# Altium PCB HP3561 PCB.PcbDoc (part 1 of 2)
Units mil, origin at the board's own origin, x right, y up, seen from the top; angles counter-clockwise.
Board outline 2229 x 3254 mil, 4 copper layers (Component Side, Signal Layer 2, Signal Layer 1, Solder Side), stack 33.234 mil thick; 84 components, 95 nets, 407 pads, 246 vias.
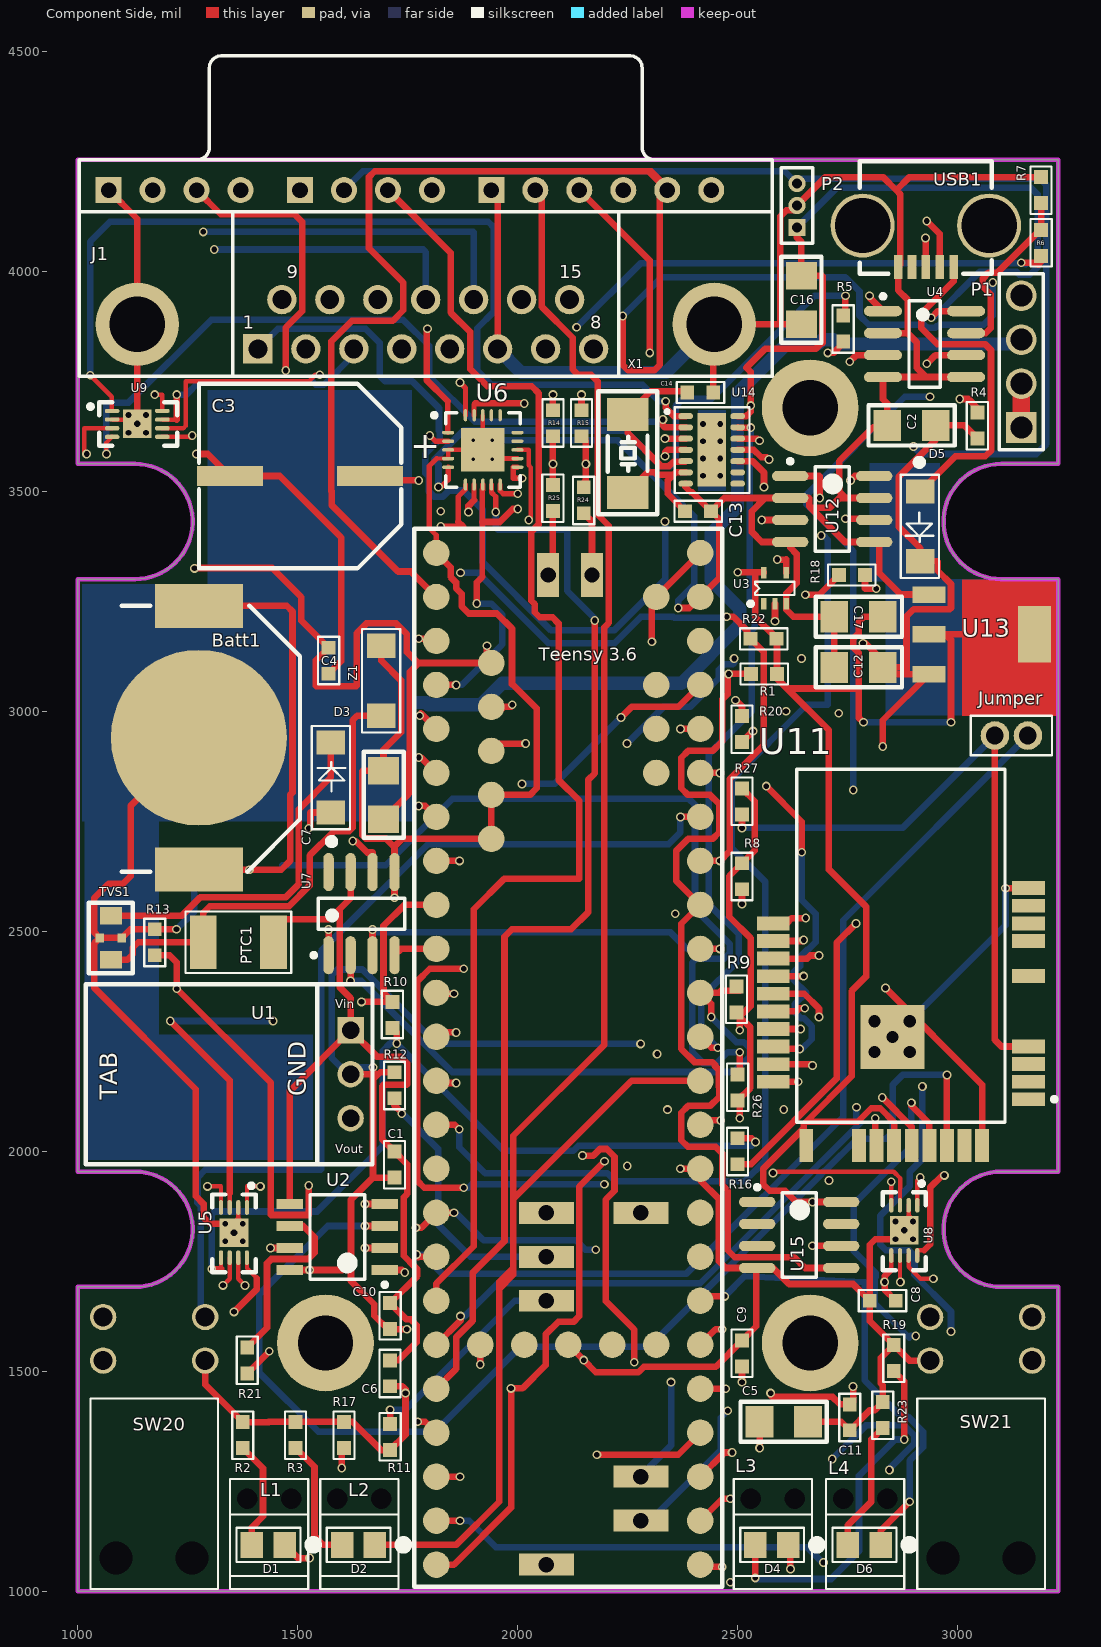
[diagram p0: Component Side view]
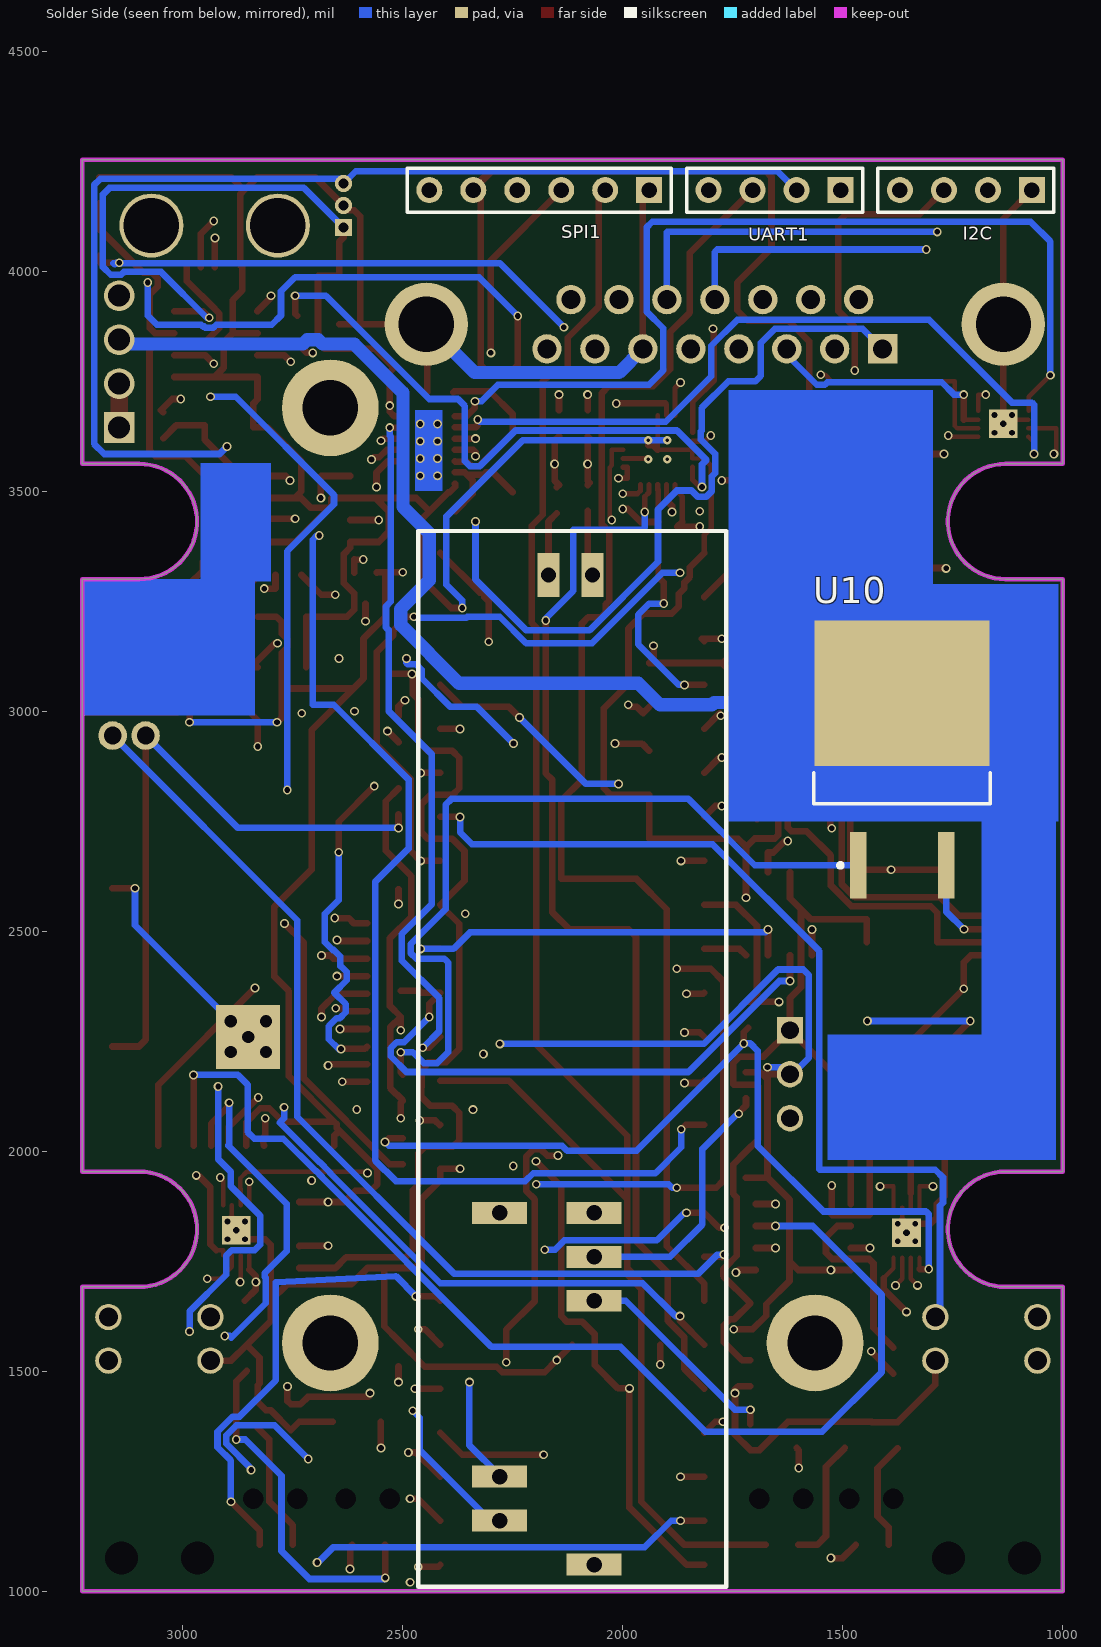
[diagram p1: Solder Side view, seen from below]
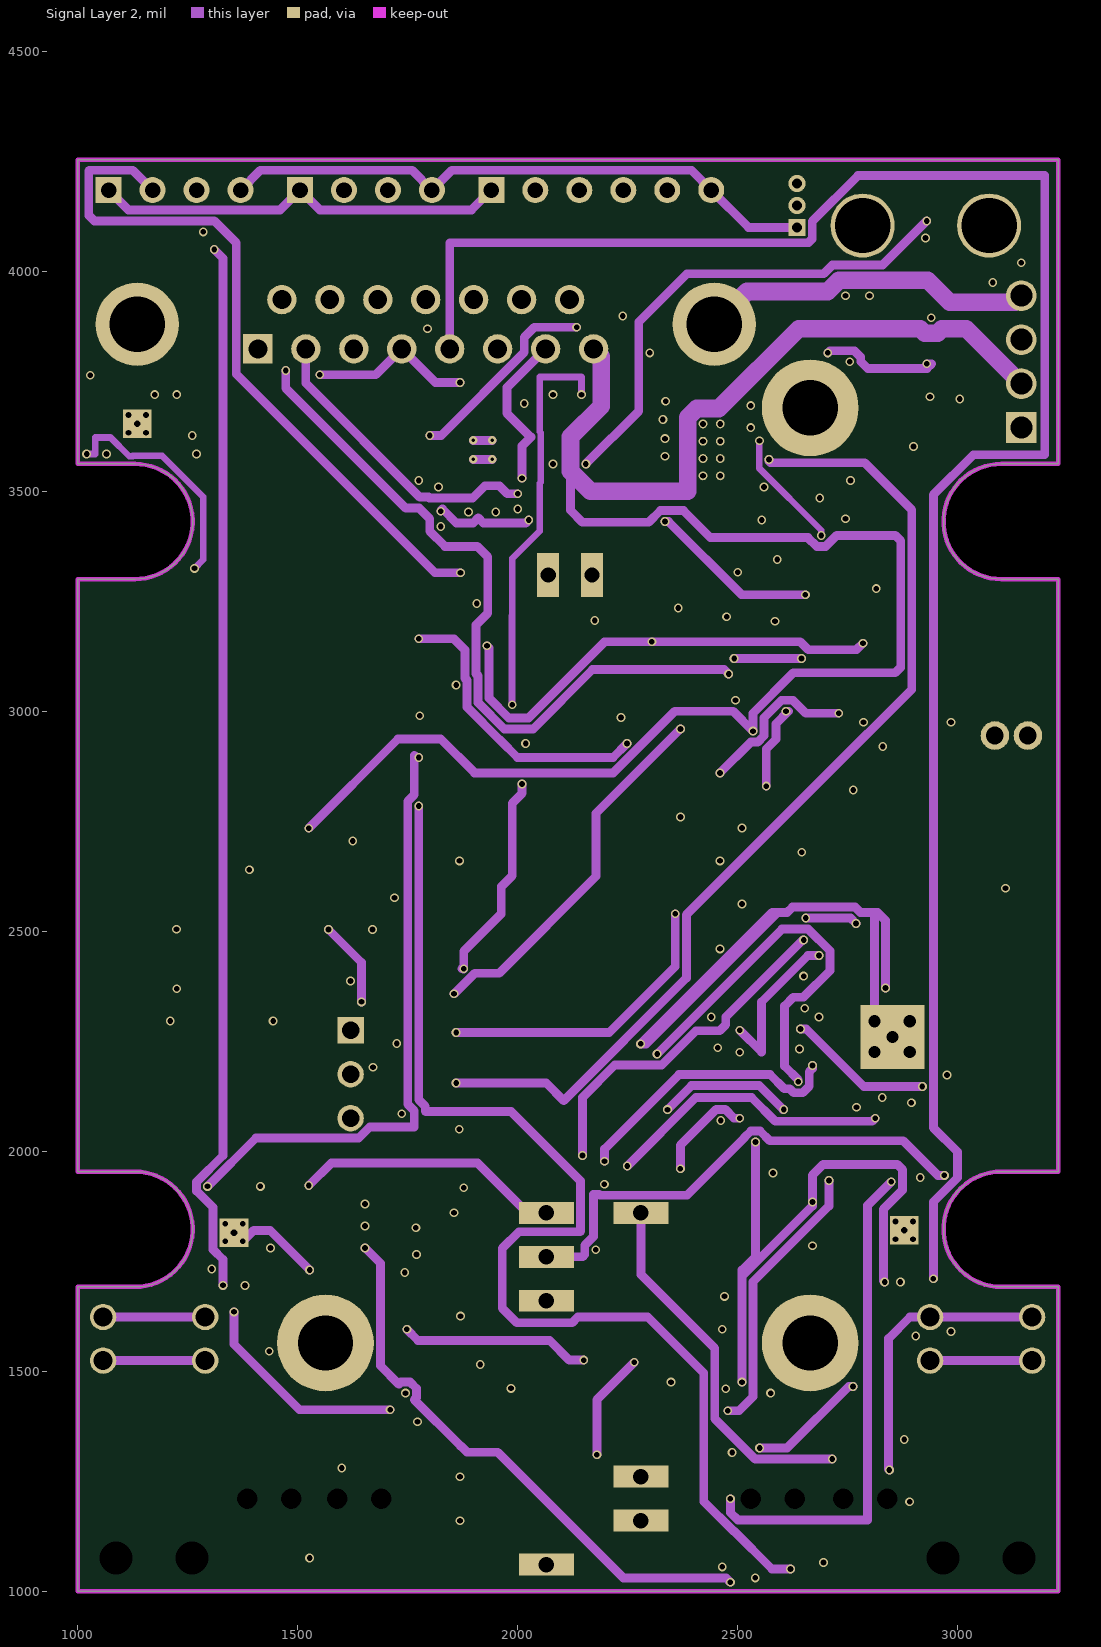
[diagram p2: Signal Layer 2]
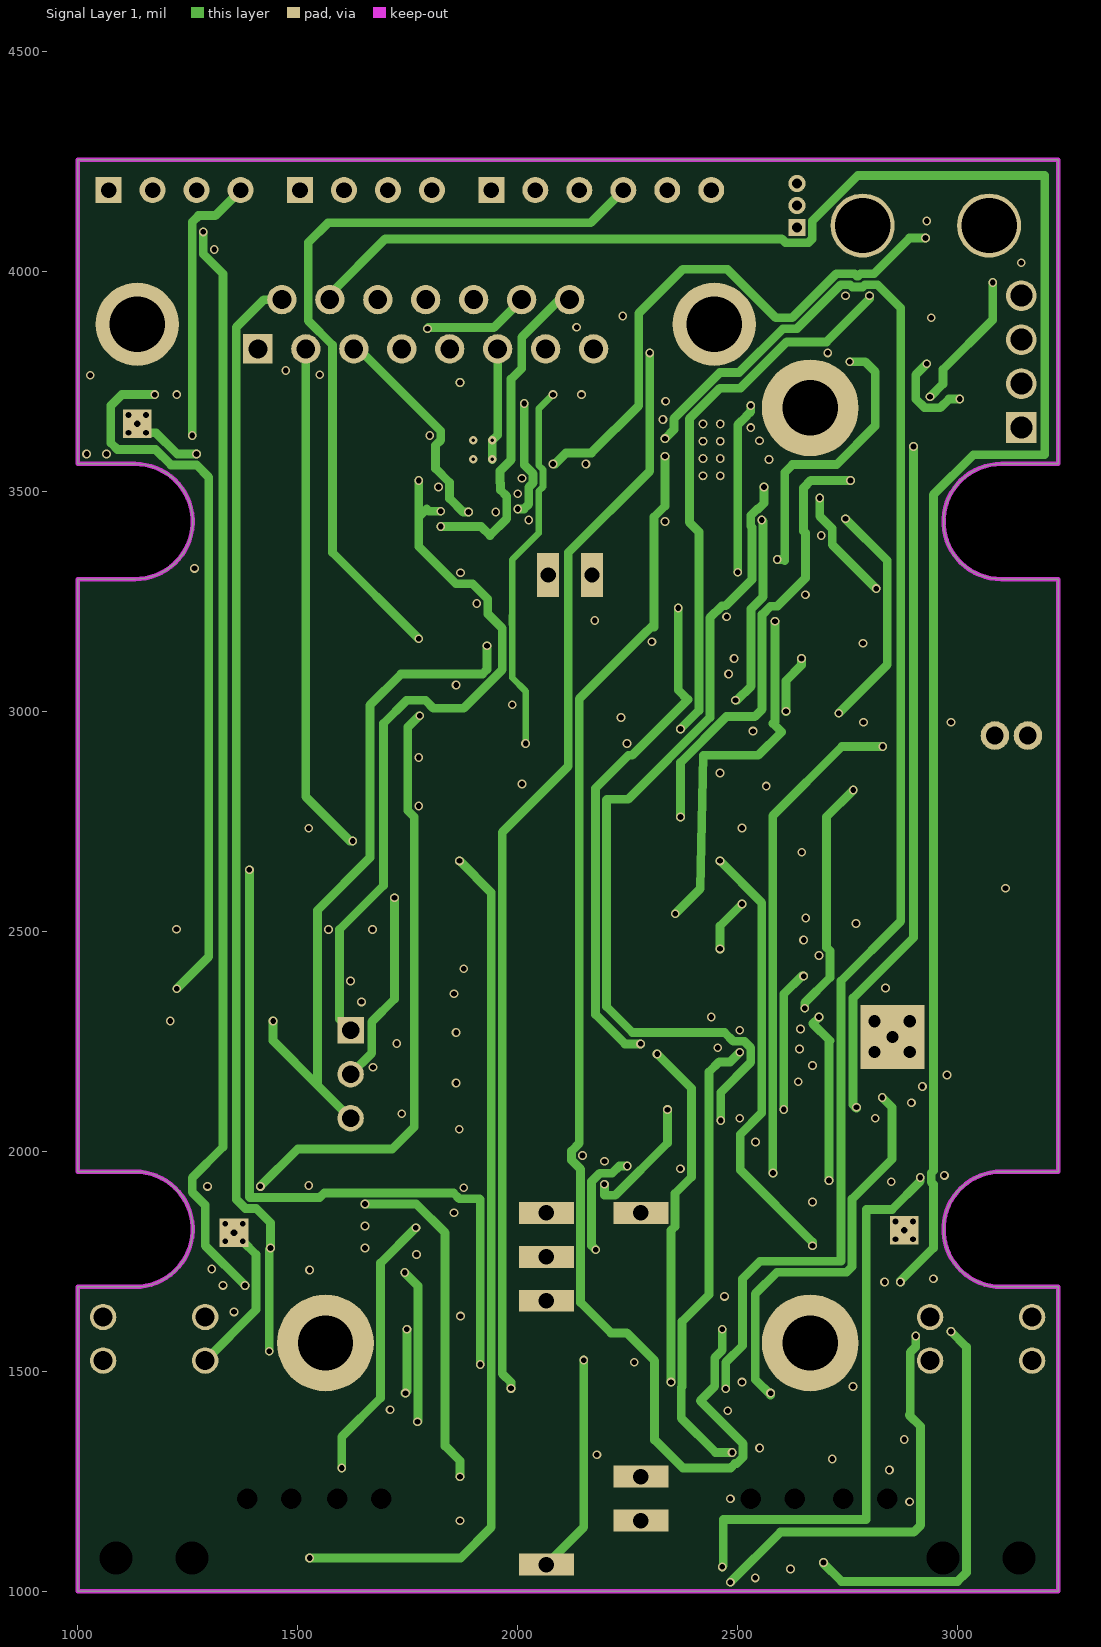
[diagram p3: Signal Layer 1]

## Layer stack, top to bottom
Top Solder: solder mask 0.4, Solder Resist, Dk 3.5
Component Side: signal copper 1.4
Dielectric 1: core 12.6, FR-4, Dk 4.8
Signal Layer 2: signal copper 1.417
Dielectric 5: prepreg 5, Dk 4.2
Signal Layer 1: signal copper 1.417
Dielectric 4: core 10, Dk 4.2
Solder Side: signal copper 1.4
Bottom Solder: solder mask 0.4, Solder Resist, Dk 3.5

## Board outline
1000,1000 1000,1691.5 1130,1691.5 ccw(c1130,1822.5) 1130,1953.5 1000,1953.5 1000,3300.5 1130,3300.5 ccw(c1130,3431.5) 1130,3562.5 1000,3562.5 1000,4254 3229,4254 3229,3562.5 3099,3562.5 ccw(c3099,3431.5) 3099,3300.5 3229,3300.5 3229,1953.5 3099,1953.5 ccw(c3099,1822.5) 3099,1691.5 3229,1691.5 3229,1000

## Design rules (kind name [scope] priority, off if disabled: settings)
Clearance [All] p1: gap=5 ignorepadtopadclearanceinfootprint=FALSE
DiffPairsRouting [All] p1: maxlimit=10 minlimit=10 mostfreqgap=10 toplayer_minwidth=15 toplayer_maxwidth=15 toplayer_prefwidth=15 midlayer1_minwidth=15 midlayer1_maxwidth=15 midlayer1_prefwidth=15 midlayer2_minwidth=15 midlayer2_maxwidth=15 midlayer2_prefwidth=15 bottomlayer_minwidth=15 bottomlayer_maxwidth=15 bottomlayer_prefwidth=15 maxuncoupledlength=500
HoleSize [All] p1: absolutevalues=TRUE maxlimit=250 minlimit=13 maxpercent=80.000 minpercent=20.000
MinimumSolderMaskSliver [All] p1: minsoldermaskwidth=1
PolygonConnect [All] p1: connectstyle=Relief reliefconductorwidth=10 reliefentries=4 polygonreliefangle="90 Angle" airgapwidth=10
RoutingVias [All] p1: holewidth=13 width=20 viastyle="Through Hole" minholewidth=13 minwidth=20 maxholewidth=28 maxwidth=50
SMDNeckDown [All] p1: percent=150.000
SilkToSilkClearance [All] p1: silktosilkclearance=1
SilkToSolderMaskClearance [IsPad] p1: minsilkscreentomaskgap=1 clearancetoexposedcopper=TRUE
SolderMaskExpansion [All] p1: expansion=4
Width [All] p1: maxlimit=100 minlimit=7 preferedwidth=20 toplayer_prefwidth=15 midlayer1_minwidth=10 midlayer2_minwidth=10 bottomlayer_minwidth=10 bottomlayer_prefwidth=15 minimp=50.000000 maximp=50.000000 favimp=50.000000
25 further rules are at their usual default settings.

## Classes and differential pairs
component class "Teensy 3.6 with J1939 - Handheld Rev3": Batt1 C7 C9 C10 C13 C14 D1 D2 D4 D6 I2C L1 L2 L3 L4 P2 R2 R3 R8 R9 R10 R11 R12 R13 R18 R19 R20 R21 R23 SW20 SW21 "Teensy 3.6" U2 U5 U7 U8 U9 U12 U14 UART1 X1
component class "Additional Circuits - Handheld - Rev 3": C1 C2 C3 C4 C5 C6 C8 C11 C12 C16 C17 D3 D5 J1 Jumper P1 PTC1 R1 R4 R5 R6 R7 R14 R15 R16 R17 R22 R24 R25 R26 R27 SPI1 TVS1 U1 U3 U4 U6 U10 U11 U13 U15 USB1 Z1
differential pair "USB D": +"USB D_P" -"USB D_N"
differential pair "Hst USB": +"Hst USB_P" -"Hst USB_N"

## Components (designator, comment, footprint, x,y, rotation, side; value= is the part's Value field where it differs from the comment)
Batt1 "CR1225" "Battery Clip - CR1225" 1275,2940 r270 top locked
C1 "0.1uF" 0603 1720,1969.53 r90 top
C2 "22uF" 1206 2895,3650 r0 top
C3 "100uF" "Elec. Cap - G" 1505,3535 r0 top locked
C4 "10uF" 0603 1570,3115 r270 top
C5 "10uF" 1206 2605,1385 r180 top
C6 "0.1uF" 0603 1710,1495 r90 top
C7 "10uF" 1206 1695,2810 r90 top
C8 "0.1uF" 0603 2830,1660 r0 top
C9 "0.1uF" 0603 2510,1540 r270 top
C10 "1uf" 0603 1710,1625 r270 top
C11 "0.1uF" 0603 2755,1395 r90 top
C12 "22uF" 1206 2775,3100 r0 top
C13 "18pF" 0603 2410,3455 r180 top
C14 "18pF" 0603 2415,3725 r180 top
C16 "22uF" 1206 2645,3935 r90 top
C17 "22uF" 1206 2775,3215 r0 top
D1 "Green" "0805 Polarized" 1435,1105 r180 top
D2 "Red" "0805 Polarized" 1640,1105 r180 top
D3 "ACURA107-HF" "SMA with A and K" 1575,2770 r90 top
D4 "Yellow" "0805 Polarized" 2580,1105 r180 top
D5 "ACURA107-HF" "SMA with A and K" 2915,3500 r270 top
D6 "Blue" "0805 Polarized" 2790,1105 r180 top
I2C "Header 4" HDR1X4#1 1070,4185 r0 bottom
J1 "Vehicle Interface Cable Connector" DSUB1.385-2H15 1790.91,4254.02 r0 top locked
Jumper "WiFi Jumper" "WiFi Jumper" 3160,2945 r180 top
L1 "SLP3" PCBComponent_1 1524,1255 r180 top locked
L2 "SLP3" PCBComponent_1 1729,1255 r180 top locked
L3 "SLP3" PCBComponent_1 2669,1255 r180 top locked
L4 "SLP3" PCBComponent_1 2879,1255 r180 top locked
P1 "Header 4" HDR1X4#2 3145,3645 r90 top
P2 "DNP GP-20U7 JST Header" MHDR1X3 2635,4100 r90 top
PTC1 "PTC RESTTBLE 0.75A" 1812 1365,2475 r0 top
R1 "4.7k" 0603 2560,3085 r180 top
R2 "330" 0603 1375,1354.53 r90 top
R3 "330" 0603 1495,1355 r90 top
R4 "4.7k" 0603 3045,3650 r90 top
R5 "47" 0603 2740,3870 r90 top
R6 "47" 0603 3190,4065 r270 top
R7 "4.7k" 0603 3190,4185 r90 top
R8 "100k" 0603 2510,2625 r90 top
R9 "100k" 0603 2497.5,2345 r270 top
R10 "4.7k" 0603 1715,2310 r270 top
R11 "100k" 0603 1710,1350 r270 top
R12 "100k" 0603 1720,2150 r90 top
R13 "100k" 0603 1175,2475 r90 top
R14 "DNP" 0603 2145,3655 r270 top
R15 "DNP" 0603 2080,3655 r270 top
R16 "100k" 0603 2500,2000 r90 top
R17 "100k" 0603 1605,1355 r90 top
R18 "1k" 0603 2760,3310 r0 top
R19 "330" 0603 2855,1530 r90 top
R20 "1k" 0603 2510,2959.53 r90 top
R21 "4.7k" 0603 1385,1524 r270 top
R22 "4.7k" 0603 2559,3165 r180 top
R23 "330" 0603 2830,1400 r90 top
R24 "47" 0603 2150,3480 r90 top
R25 "47" 0603 2080,3485 r90 top
R26 "100k" 0603 2500,2144.53 r270 top
R27 "100k" 0603 2510,2795 r270 top
SPI1 "Header 6" HDR1X6 1940,4185 r0 bottom
SW20 "PB400" PB400 1057.5,1623 r270 top locked
SW21 "PB400" PB400 2937.5,1623 r270 top locked
"Teensy 3.6" "Teensy 3.6" "Teensy 3.6 Surface Mount" 1815,2060 r0 top locked
TVS1 "Varistor 26V" Transfeed 1075,2535 r270 top
U1 "OKI-78SR" OKI-78SR 1620,2075 r90 top locked
U2 "NCV7356D1R2G" ONSC-SOIC-8-751-07_V 1590,1805 r180 top
U3 "74AHCT1G14" SOT-353 2585,3280 r0 top
U4 "SN75HVD08DR" SOIC-SN8_N 2925,3835 r0 top
U5 "MCP2558" TDFN 1355,1815 r180 top
U6 "ADG1634BCPZ-REEL7" ADI-CP-20-4_N 1920.63,3594.41 r0 top
U7 "MCP2003A-E/SN" SOIC-SN8_N 1645,2540 r90 top
U8 "MCP2558" TDFN 2878.89,1820 r180 top locked
U9 "MCP2558" TDFN 1135,3653.47 r270 top
U10 "BTS141TC" INF-PG-TO263-3-2_N 1365,2890 r90 bottom
U11 "ATML-ATWINC1500-MR210PA-28" ATML-ATWINC1500-MR210PA-28_V 2871,2305.47 r180 top locked
U12 "MOCD207R2M" SOIC-8 2715,3460 r0 top
U13 "NCP1117LPST33" SOT-223 2934.84,3265.55 r270 top
U14 "MCP2517FD" SOP14 2381.89,3671.18 r0 top
U15 "ATECC608A" SOIC-8 2640,1809.53 r0 top
UART1 "Header 4" HDR1X4#1 1505,4185 r0 bottom
USB1 "UX60SC-MB-5S8" "USB Mini UX60S" 2927.99,4250.16 r180 top locked
X1 "16MHz" "XTAL 2 pad" 2250,3497.83 r90 top locked
Z1 "SMA6J" SMA 1690,3149 r270 top

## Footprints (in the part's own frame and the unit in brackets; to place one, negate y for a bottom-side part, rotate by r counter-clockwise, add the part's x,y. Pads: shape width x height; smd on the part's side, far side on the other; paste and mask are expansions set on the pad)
0603 [mm] "0603 SMP Component with outline"
  rect 0.8x0.8 smd: 1(-0.75,0) 2(0.75,0)
  silkscreen extent -1.39,-0.61 1.36,0.61
"0805 Polarized" [mm] "Polarized 0805 with Pin 1 as Anode (+)"
  rect 1.3x1.5 smd: 1(-0.899,0) 2(1.001,0)
  silkscreen extent -2.79,-0.99 1.88,0.99
1206 [mm]
  rect 1.6x1.8 smd: 1(-1.4,0) 2(1.4,0)
  silkscreen extent -2.47,-1.16 2.5,1.15
1812 [mil] "Used for PTC Fuses from belfuse"
  rect 60x122 smd: 1(-80,0)
  rect 62x122 smd: 2(80,0)
  silkscreen extent -120,-70 120,70
ADI-CP-20-4_N [mm] "QFN, 20-Leads, Body 4x4mm, Pitch 0.5mm, Thermal Pad 2.5x2.5mm, IPC Medium Density"
  oval 0.7x0.2 smd: 1(-2,1) 2(-2,0.5) 3(-2,0) 4(-2,-0.5) 5(-2,-1) 11(2,-1) 12(2,-0.5) 13(2,0) 14(2,0.5) 15(2,1)
  oval 0.2x0.7 smd: 6(-1,-2) 7(-0.5,-2) 8(0,-2) 9(0.5,-2) 10(1,-2) 16(1,2) 17(0.5,2) 18(0,2) 19(-0.5,2) 20(-1,2)
  rect 2.5x2.5 smd: 21(0,0)
  silkscreen extent -2.92,-2.15 2.15,2.15, body extent -2,-2 2,2, height 1
ATML-ATWINC1500-MR210PA-28_V [mm] "Module, 28-Leads, Body 21.72x14.73mm, Pitch 1.016mm"
  rect 1.9x0.8 smd: 1(-7.365,4.761) 2(-7.365,3.745) 3(-7.365,2.729) 4(-7.365,1.713) 5(-7.365,-2.351) 6(-7.365,-4.383) 7(-7.365,-5.399) 8(-7.365,-6.415) 9(-7.365,-7.431) 10(7.365,-5.393) 11(7.365,-4.377) 12(7.365,-3.361) 13(7.365,-2.345) 14(7.365,-1.329) 15(7.365,-0.313) 16(7.365,0.703) 17(7.365,1.719) 18(7.365,2.735) 19(7.365,3.751)
  rect 0.8x1.9 smd: 20(5.465,7.431) 21(2.417,7.431) 22(1.401,7.431) 23(0.385,7.431) 24(-0.631,7.431) 25(-1.647,7.431) 26(-2.663,7.431) 27(-3.679,7.431) 28(-4.695,7.431)
  rect 3.7x3.7 hole 0.711: 29(0.485,1.161)
  silkscreen extent -8.99,-14.29 6.01,6.08, body extent -7.36,-14.29 7.36,7.43, height 3.35
"Battery Clip - CR1225" [mil] "Battery Holder Outlline for CR2032"
  rect 100x200 smd: 1(-300,0) 1(300,0)
  round 400 smd: 2(0,0)
  silkscreen extent -300,-175 305,230
DSUB1.385-2H15 [mm] "Connector; D Subminiature; 15 Position; Right Angle; Pitch 1.385 mm"
  rect 1.69x1.69 hole 1.09: 1(-9.695,-10.92)
  round 1.69 hole 1.09: 2(-6.925,-10.92) 3(-4.155,-10.92) 4(-1.385,-10.92) 5(1.385,-10.92) 6(4.155,-10.92) 7(6.925,-10.92) 8(9.695,-10.92) 9(-8.31,-8.08) 10(-5.54,-8.08) 11(-2.77,-8.08) 12(0,-8.08) 13(2.77,-8.08) 14(5.54,-8.08) 15(8.31,-8.08)
  round 4.8 hole 3.18: 16(-16.66,-9.5) 17(16.66,-9.5)
  silkscreen extent -20,-12.5 20,6
"Elec. Cap - G" [mil] "Panasonic Style Electrolytic capacitor, Can size G, 10mm diameter"
  rect 150x45 smd: 1(159.45,0) 2(-159.45,0)
  silkscreen extent -229,-210 231,210
HDR1X4#1 [mm] "Connector; Header; 4 Position"
  rect 1.5x1.5 hole 0.9: 1(0,0)
  round 1.5 hole 0.9: 2(2.54,0) 3(5.08,0) 4(7.62,0)
  silkscreen extent -1.27,-1.27 8.89,1.27
HDR1X4#2 [mm] "Connector; Header; 4 Position"
  rect 1.778x1.778 hole 1.27: 1(0,0)
  round 1.778 hole 1.27: 2(2.54,0) 3(5.08,0) 4(7.62,0)
  silkscreen extent -1.27,-1.27 8.89,1.27
HDR1X6 [mm] "Connector; Header; 6 Position"
  rect 1.5x1.5 hole 0.9: 1(0,0)
  round 1.5 hole 0.9: 2(2.54,0) 3(5.08,0) 4(7.62,0) 5(10.16,0) 6(12.7,0)
  silkscreen extent -1.27,-1.27 13.97,1.27
INF-PG-TO263-3-2_N [mm] "DPAK, 3-Leads, Body 10x9.25mm, Pitch 2.54mm, IPC Medium Density"
  rect 3.85x0.95 smd: 1(-6.1,2.54) 3(-6.1,-2.54)
  rect 8.4x10.1 smd: 2(3.85,0)
  silkscreen extent -6.22,-5.1 -0.75,5.1, body extent -2.55,-5.1 6.9,5.1, height 4.4
MHDR1X3 [mm] "Connector; Header; 3 Position"
  rect 1x1 hole 0.6: 1(0,0)
  round 1 hole 0.6: 2(1.27,0) 3(2.54,0)
  silkscreen extent -0.9,-0.9 3.44,0.9
OKI-78SR [mil] "Horizontal Mount SIP DC/DC Converter"
  rect 60x60 hole 40: 1(200,0)
  round 60 hole 40: 2(100,0) 3(0,0)
  silkscreen extent -105,-50 305,602
ONSC-SOIC-8-751-07_V [mm] "SOIC, 8-Leads, Body 4.9x3.9mm, Pitch 1.27mm"
  rect 1.52x0.6 smd: 1(-2.74,1.905) 2(-2.74,0.635) 3(-2.74,-0.635) 4(-2.74,-1.905) 5(2.74,-1.905) 6(2.74,-0.635) 7(2.74,0.635) 8(2.74,1.905)
  silkscreen extent -2.87,-2.45 1.58,2.88, body extent -1.95,-2.45 1.95,2.45, height 1.75
PB400 [mil]
  round 60 hole 43: 1(0,0) 2(99,0) 3(0,232) 4(99,232)
  round 0 hole 75: ""(548,29.5) ""(548,202.5)
  silkscreen extent 185,-29 618,261
PCBComponent_1 [mil]
  round 0 hole 46: ""(39,45) ""(139,45)
  silkscreen extent 0,0 178,250
SMA [mil] "SMA with outline"
  rect 55x65 smd: 1(0,0) 2(159,0)
  silkscreen extent -38,-44 197,43
"SMA with A and K" [mil] "SMA with outline and Cathode Bar on Pin 2"
  rect 55x65 smd: 1(0,0) 2(159,0)
  silkscreen extent -71,-44 197,43
SOIC-8 [mm]
  oval 2.1x0.6 smd: 1(-2.425,1.905) 2(-2.425,0.635) 3(-2.425,-0.635) 4(-2.425,-1.905) 5(2.425,-1.905) 6(2.425,-0.635) 7(2.425,0.635) 8(2.425,1.905)
  silkscreen extent -2.55,-2.45 0.98,2.88
SOIC-SN8_N [mm] "SOIC, 8-Leads, Body 4.9x3.8mm, Pitch 1.27mm, IPC Medium Density"
  oval 2.2x0.6 smd: 1(-2.4,1.905) 2(-2.4,0.635) 3(-2.4,-0.635) 4(-2.4,-1.905) 5(2.4,-1.905) 6(2.4,-0.635) 7(2.4,0.635) 8(2.4,1.905)
  silkscreen extent -2.52,-2.5 0.9,2.88, body extent -2,-2.5 2,2.5, height 1.75
SOP14 [mm]
  oval 0.85x0.35 smd: 1(0,0) 2(0,-0.65) 3(0,-1.3) 4(0,-1.95) 5(0,-2.6) 6(0,-3.25) 7(0,-3.9) 8(3,-3.9) 9(3,-3.25) 10(3,-2.6) 11(3,-1.95) 12(3,-1.3) 13(3,-0.65) 14(3,0)
  round 0.508 hole 0.33: ""(1,-3.45) ""(1,-2.45) ""(1,-1.45) ""(1,-0.45) ""(2,-3.45) ""(2,-2.45) ""(2,-1.45) ""(2,-0.45)
  rect 1.65x4.25 smd: ""(1.5,-1.95)
  silkscreen extent -1.14,-4.44 3.68,0.51
SOT-223 [mm]
  rect 0.95x1.9 smd: 1(0,0) 2(2.3,0) 3(4.6,0)
  rect 3.25x1.9 smd: 4(2.3,6.1)
SOT-353 [mil]
  rect 12x26 smd: 1(-25.59,-35.43) 2(0,-35.43) 3(25.59,-35.43) 4(25.59,35.43) 6(-25.59,35.43)
  silkscreen extent -61,-40 44,15
TDFN [mm] "8-Lead Plastic Dual Flat, No Lead Package (MN) – 2x3x0.75mm Body [TDFN]"
  rect 1.651x1.651 hole 0.381: 0(0,0)
  oval 0.25x0.85 smd: 1(-0.75,-1.45) 2(-0.25,-1.45) 3(0.25,-1.45) 4(0.75,-1.45) 5(0.75,1.45) 6(0.25,1.45) 7(-0.25,1.45) 8(-0.75,1.45)
  silkscreen extent -1.25,-2.83 1.25,2.3
"Teensy 3.6 Surface Mount" [mil] "32 bit Arduino Compatible Microcontroller www.pjrc.com/teensy"
  round 60 smd: 1(0,0) 2(0,100) 3(0,200) 4(0,300) 5(0,400) 6(0,500) 7(0,600) 8(0,700) 9(0,800) 10(0,900) 11(0,1000) 12(0,1100) 13(0,1200) 14(0,1300) 15(100,-500) 16(0,-100) 17(300,-500) 18(400,-500) 19(600,-300) 20(600,0) 21(600,100) 22(600,200) 23(600,300) 24(600,400) 25(600,500) 26(600,600) 27(600,700) 28(600,800) 29(600,900) 30(600,1000) 31(600,1100) 32(600,1200) 33(600,1300) 34(500,1200) 35(500,1000) 36(500,900) 37(500,800) 38(0,-200) 39(0,-300) 40(0,-400) 41(0,-500) 42(0,-600) 43(0,-700) 44(0,-800) 45(0,-900) 46(0,-1000) 47(600,-1000) 48(600,-900) 49(600,-600) 50(600,-500) 51(600,-400) 61(600,-200) 62(600,-800) 63(600,-700) 75(125,1050) 76(125,950) 77(125,850) 78(125,750) 79(125,650) 88(500,-500) 90(600,-100) 91(200,-500)
  rect 125x50 hole 35: 52(250,-200) 53(250,-300) 54(250,-400) 59(250,-1000) 68(465,-200) 72(465,-800) 74(465,-900)
  rect 50x100 hole 35: 82(354,1250)
  rect 50x100 hole 35 paste+10: 83(254,1250)
  silkscreen extent -50,-1050 650,1355
Transfeed [mil] "AVX Multilayer Ceramic Transient Voltage Suppressors"
  rect 40x50 smd: 1(0,0) 2(100,0)
  rect 20x20 smd: 3(50,25) 3(50,-25)
  silkscreen extent -30,-50 130,50
"USB Mini UX60S" [mm] "Receptacle - Standard - Shell through Hole"
  round 3.7 hole 3.2: 0(-3.65,3.7) 0(3.65,3.7)
  rect 0.5x1.4 smd: 1(-1.6,6.1) 2(-0.8,6.1) 3(0,6.1) 4(1.6,6.1) 5(0.8,6.1)
  silkscreen extent -3.81,0 3.81,6.48
"WiFi Jumper" [mil]
  round 65 hole 40: 1(0,0) 2(75,0)
  silkscreen extent -55,-45 130,45
"XTAL 2 pad" [mm] "Digikey XC1659CT-ND"
  rect 1.9x2.4 smd: 1(0,0) 2(4.5,0)
  silkscreen extent -1.27,-1.7 5.84,1.7

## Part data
Batt1: library part "CR2032 Battery Holder", "Lithium Battery Non-Rechargeable (Primary) 3V Coin, 12.5mm", Manufacturer=Linx, PartNumber=BAT-HLD-012-SMT, Supplier Part Number 1=BAT-HLD-012-SMT-ND
C1 C9 C11: library part Cap, "CAP CER 0.1UF 50V X7R 0603", Manufacturer="Murata Electronics North America", PartNumber=GRM188R71H104KA93D, Supplier Part Number 1=490-1519-1-ND
C2 C12 C16 C17: library part Cap, "22µF ±20% 25V Ceramic Capacitor X5R 1206 (3216 Metric)", Manufacturer="Murata Electronics North America", PartNumber=GRT31CR61E226ME01L, Supplier Part Number 1=490-12451-1-ND
C3: library part "Tantalum Cap_1", "Aluminum Electrolytic Capacitors Radial, Can - SMD 5000 Hrs @ 105°C", Manufacturer="Panasonic Electronic Components", PartNumber=EEE-HC1H101P, Supplier Part Number 1=P19732CT-ND
C4: library part Cap, "10µF ±20% 25V Ceramic Capacitor X5R 0603 (1608 Metric)", Manufacturer="Murata Electronics North America", PartNumber=GRT188R61E106ME13D, Supplier Part Number 1=490-12323-1-ND
C5 C7: library part Cap, "10µF ±20% 50V Ceramic Capacitor X5R 1206 (3216 Metric)", Manufacturer="Murata Electronics North America", PartNumber=GRT31CR61H106ME01L, Supplier Part Number 1=490-12457-1-ND
C6 C8: library part Cap, "CAP CER 0.1UF 50V 10% X7R 0603", Manufacturer="Murata Electronics North America", PartNumber=GRM188R71H104KA93D, Supplier Part Number 1=490-1519-1-ND
C10: library part Cap, "1µF ±20% 50V Ceramic Capacitor X5R 0603 (1608 Metric)", Manufacturer="Murata Electronics North America", PartNumber=GRT188R61H105ME13D, Supplier Part Number 1=490-12331-1-ND
C13 C14: library part Cap, "CAP CER 18PF 50V 5% NP0 0603", Manufacturer=Kemet, PartNumber=C0603C180J5GACTU, Supplier Part Number 1=399-1052-1-ND
D1: library part "LED - SMD", "LED GREEN DIFFUSED 0805 SMD", Manufacturer="OSRAM Opto Semiconductors Inc.", PartNumber="LG R971-KN-1", Supplier Part Number 1=475-1410-1-ND
D2: library part "LED - SMD", "LED RED DIFFUSED 0805 SMD", Manufacturer="OSRAM Opto Semiconductors Inc.", PartNumber="LS R976-NR-1", Supplier Part Number 1=475-1278-1-ND
D3 D5: library part "Schottky Diode", "Diode Schottky 1000V 1A Surface Mount DO-214AC (SMA)", Manufacturer="Comchip Technology", Supplier Part Number 1=641-1884-1-ND
D4 D6: library part "LED - SMD", "LED YELLOW DIFFUSED 0805 SMD", Manufacturer="OSRAM Opto Semiconductors Inc.", PartNumber="LY R976-PS-36", Supplier Part Number 1=475-2560-1-ND
I2C P1 UART1: "Header, 4-Pin"
J1: library part "D Connector 15", "Receptacle Assembly, 15 Position, Right Angle", Manufacturer="Amphenol FCI", PartNumber=D15S33E4GV00LF, Supplier Part Number 1=609-1498-ND
P2: library part MHDR1X3, "CONN HEADER PH SIDE 3POS 2MM SMD", Manufacturer=JST, PartNumber=S3B-PH-SM4-TB(LF)(SN), Supplier Part Number 1=455-1750-1-ND
PTC1: library part PTC, "PTC RESTTBLE 0.75A 33V CHIP 1812", Manufacturer="Bel Fuse Inc.", PartNumber=0ZCG0075BF2B, Supplier Part Number 1=507-1765-1-ND
R1 R4 R7 R10 R21 R22: library part "Chip Resistor", "±1% 0.1W, 1/10W Chip Resistor 0603 (1608 Metric) Automotive AEC-Q200, High Voltage Thick Film", Manufacturer="Rohm Semiconductor", PartNumber=KTR03EZPF4701, Supplier Part Number 1=RHM4.7KAYCT-ND
R2 R3 R18 R19 R23: library part "Chip Resistor", "330 Ohms ±1% 0.1W, 1/10W Chip Resistor 0603 (1608 Metric) Automotive AEC-Q200, High Voltage Thick Film", Manufacturer="Rohm Semiconductor", PartNumber=KTR03EZPF3300, Supplier Part Number 1=RHM330AYCT-ND
R5 R6 R24 R25: library part "Chip Resistor", "±1% 0.1W, 1/10W Chip Resistor 0603 (1608 Metric) Automotive AEC-Q200, High Voltage Thick Film", Manufacturer="Rohm Semiconductor", PartNumber=KTR03EZPF47R0, Supplier Part Number 1=RHM47AYCT-ND
R8 R9 R11 R12 R13 R16 R17 R26 R27: library part "Chip Resistor", "±1% 0.1W, 1/10W Chip Resistor 0603 (1608 Metric) Automotive AEC-Q200, High Voltage Thick Film", Manufacturer="Rohm Semiconductor", PartNumber=KTR03EZPF1003, Supplier Part Number 1=RHM100KAYCT-ND
R14 R15: library part "Chip Resistor", "RES SMD 47 OHM 1% 1/10W 0603", Manufacturer="Panasonic Electronic Components", PartNumber=ERJ-3EKF47R0V, Supplier Part Number 1=P47.0HCT-ND
R20: library part "Chip Resistor", "1000 Ohms ±1% 0.1W, 1/10W Chip Resistor 0603 (1608 Metric) Automotive AEC-Q200, High Voltage Thick Film", Manufacturer="Rohm Semiconductor", PartNumber=KTR03EZPF3300, Supplier Part Number 1=RHM330AYCT-ND
SPI1: "Header, 6-Pin"
"Teensy 3.6": "32 Bit Arduino-Compatible Microcontroller", Manufacturer=PRJC, Supplier Part Number 1=DEV-13736
TVS1: library part Transfeed, "34.5V 80A Varistor 1 Circuit Surface Mount 0805 (2012 Metric)", Manufacturer=AVX, PartNumber=V2AF126C600Y2EDP, Supplier Part Number 1=478-10038-1-ND
U1: library part 7805, "5V DC/DC Converter (7805 replacement)", Manufacturer="Murata Power Solutions Inc.", PartNumber=OKI-78SR-5/1.5-W36H-C, Supplier Part Number 1=811-2692-ND
U2: library part NCV7356D1G, "Single Wire CAN Transceiver, 5 to 27 V, 8-Pin SOIC, Pb-Free, Tube", Manufacturer="On Semiconductor", Supplier Part Number 1=NCV7356D1R2GOSCT-ND
U3: library part "74AHCT1G14 Inverter", "IC SCHMIT-TRIGG INV GATE SOT353", Manufacturer="Diodes Incorporated", PartNumber=74AHCT1G14SE-7, Supplier Part Number 1=74AHCT1G14SE-7DICT-ND
U4: library part "SN75HVD12D (3.3v RS485)", "IC RS485 TXRX 3/5V 8-SOIC", Manufacturer="Texas Instruments", Supplier Part Number 1=296-37893-1-ND
U5 U8 U9: library part MCP2558FD, "Microchip CAN FD Transceiver with Silent Mode", Manufacturer=Microchip, PartNumber=MCP2558FDT-H/MNY
U6: "IC SWITCH QUAD SPDT 20LFCSP", Manufacturer="Analog Devices", Supplier Part Number 1=ADG1634BCPZ-REEL7CT-ND
U7: library part MCP2003AT-E/SN, "LIN J2602 Transceiver, 8-Pin SOIC, Extended Temperature, Tape and Reel", Manufacturer=Microchip, Supplier Part Number 1=MCP2003A-E/SN-ND
U10: "Smart Low-Side Power Switch HITFET, 60 V VDS, 12 A ID, -40 to 150 degC, PG-TO263-3-2, Reel, Green", Manufacturer=Infineon, Supplier Part Number 1=BTS141TCTR-ND
U11: "SMARTCONNECT ATWINC1500B-MU-T MO", Manufacturer="Microchip Technologies", PartNumber=ATWINC1510-MR210PB1140, Supplier Part Number 1=ATWINC1510-MR210PB1140-ND
U12: library part "Optoisolator - Dual", "Optoisolator Transistor Output 2500Vrms 2 Channel 8-SO Tall", Manufacturer="Fairchild/ON Semiconductor", Supplier Part Number 1=MOCD207R2MCT-ND
U13: library part "NCP1117 2.5V", "Linear Voltage Regulator IC Positive Fixed Output 3.3V 1A SOT-223", Manufacturer="On Semiconductor", PartNumber=NCP1117LPST33T3G, Supplier Part Number 1=NCP1117LPST33T3GOSCT-ND
U15: library part ATECC508A, "Authentication Chip IC Networking and Communications 8-SOIC", Manufacturer="Microchip Technology", PartNumber=ATECC508A-SSHDA-T, Supplier Part Number 1=ATECC508A-SSHDA-TCT-ND
USB1: library part USB-Rugged, "USB - mini B USB 2.0 Receptacle Connector 5 Position Surface Mount, Right Angle; Through Hole", Manufacturer=Hirose, Supplier Part Number 1=H11589CT-ND
X1: library part "Crystal Oscillator", "CRYSTAL 16MHZ 18PF SMD", Manufacturer="TXC CORPORATION", PartNumber=7A-16.000MAAJ-T, Supplier Part Number 1=887-1086-1-ND
Z1: library part "Zener - Bidirectional", "TVS DIODE 20VWM 36.8VC SMA", Manufacturer="Micro Commercial Co", PartNumber=SMA6J24CA-TP, Supplier Part Number 1=SMA6J24CA-TPMSCT-ND

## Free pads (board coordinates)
  round 220 hole 126: 0(1563,1564) 0(2665,1564) 0(2665,3690)

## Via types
v1: diameter 20, hole 13, Component Side to Solder Side, 238 vias
v2: diameter 19.68, hole 7.87, Component Side to Solder Side, 4 vias
v3: diameter 50, hole 28, Component Side to Solder Side, 4 vias

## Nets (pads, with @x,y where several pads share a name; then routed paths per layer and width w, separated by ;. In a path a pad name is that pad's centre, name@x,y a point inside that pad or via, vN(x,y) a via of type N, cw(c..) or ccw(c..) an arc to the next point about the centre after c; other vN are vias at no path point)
3V3: C8.2 C9.2 C16.2 C17.2 I2C.4 P2.1 R1.1 R10.2 R16.2 R22.1 SPI1.6 U3.6 U4.8 U5.5 U8.5 U9.5 U11.20 U11.23 U13.2 U13.4 U14.14 U15.8 UART1.4 | length 10904.5
  Component Side w10: U9.5@1192.09,3623.94 v1@1257,3623.94 ; 1325.47,1733 U5.5@1325.47,1757.91 ; 2849.36,1731 U8.5@2849.36,1762.91
  Component Side w14.76: v1(1304.25,1732) 1324.47,1732 1325.47,1733 ; 2847,1728.64 2849.36,1731
  Component Side w15: v1@1257,3623.94 v1(1260,3626.94) ; R10.2@1715,2280.47 1725,2270.47 v1(1725,2245) ; R16.2@2500,2029.53 2532.07,2029.53 v1(2540.6,2021) ; U14.14@2500,3671.18 2520,3671.18 2530,3681.18 v1(2530,3695) 2530,3771.5 2520,3781.5 2562.5,3824 2677.18,3824 2690.68,3837.5 2693,3837.5 2693,3989.12 2692,3990.12 C16.2@2645,3990.12 2645,4067.15 2635,4077.15 P2.1@2635,4100 ; v1(2500.18,3316) 2541,3316 ; v1(2510,1475) C9.2@2510,1510.47 ; U3.6@2559.41,3315.43 2559.41,3316 2541,3316 ; U11.20@2649.98,2041.71 2655.84,2035.85 U11.20@2655.84,2012.91 ; U15.8@2735.47,1884.53 v1(2670,1884.53) 2633.47,1884.53 2608,1910 2573,1910 2558,1925 2558,1959.82 2649.98,2051.8 2649.98,2061.14 2655.84,2067 ; v1(2786,2975) 2775,2986 2775,3052 ; C17.2@2830.12,3215 2787.5,3215 2775,3202.5 2775,3176.82 2762.5,3164.32 2762.5,3145.68 2775,3133.18 2775,3052 ; 2847,1728.64 2834.2,1715.83 v1(2834.2,1702.81) 2834.2,1685.33 C8.2@2859.53,1660 ; U11.23@2855.84,2012.91 2855.84,2066 2824.34,2097.5 2803.65,2097.5 2773.15,2067 2655.84,2067 ; U13.2@2934.84,3175 2972.5,3175 ; v1(2940,3895) 2955,3910 U4.8@3019.49,3910 ; v1(2985,2975) 2985,3162.5 2972.5,3175 ; U13.4@3175,3175 2972.5,3175 ; 2541,3316 2540,3315 2540,3214.82 2589.53,3165.29 R1.1@2589.53,3085 2589.53,3074.97 2612.5,3052 ; 2612.5,3052 2707.5,2957 2707.5,2640.5 2792,2556 2792,2396.86 2759.07,2363.93 2759.07,2170.23 2655.84,2067 ; 2612.5,3052 2775,3052
  Signal Layer 2 w20: I2C.4@1370,4185 1415,4230 1760,4230 UART1.4@1805,4185 1850,4230 2395,4230 SPI1.6@2440,4185 2525,4100 P2.1@2635,4100 ; v1(2510,1475) 2510,1715.39 ; v1(2540.6,2021) 2540.6,1760.6 2510,1730 2510,1715.39 ; v1(2834.2,1702.81) 2831.39,1705.61 2831.39,1867.61 2831,1868 2875,1912 2875,1957.5 2862.5,1970 2695,1970 2670,1945 v1(2670,1884.53) 2670,1875.39 2510,1715.39
  Signal Layer 1 w20: v1(1260,3626.94) 1260,4112.5 1274.5,4127 1312,4127 I2C.4@1370,4185 ; v1(2500.18,3316) 2500.18,3651.18 2520.18,3671.18 2520,3671.36 2530,3681.36 v1(2530,3695)
  Solder Side w15: v1(1304.25,1732) 1304.25,1856.25 1311,1863 1544,1863 1693.5,2012.5 1693.5,2228.5 1710,2245 v1(1725,2245) 1968.97,2001.03 2126.71,2001.03 2138.18,2012.5 2532.1,2012.5 v1(2540.6,2021) ; P2.1@2635,4100 2725,4190 3167,4190 3182,4175 3182,4010.18 3164.32,3992.5 3140.68,3992.5 3134.18,3999 3050,3999 2946,3895 v1(2940,3895) ; v1(2786,2975) v1(2985,2975)
5V0: "Teensy 3.6.33" "Teensy 3.6.34" "Teensy 3.6.75" C2.2 C4.1 C7.1 C12.2 D5.2 R4.1 U1.3 U5.3 U8.3 U9.3 U13.3 | length 8613.5
  Component Side w10: v1(1020,3585) 1015,3585 1015,3643.62 U9.3@1077.91,3643.62 ; U5.3@1345.16,1872.09 1345.16,1904.09 ; v1(2580.64,1950.64) 2583.5,1953.5 2854.78,1953.5 2869.36,1938.92 2869.36,1915.31 2869.05,1915 U8.3@2869.05,1877.09
  Component Side w15: v1(1210,2296) 1345.16,2160.84 1345.16,1904.09 ; v1(1265,3325) 1265.91,3325.91 1441.91,3325.91 1508,3259.82 1508,3206.53 C4.1@1570,3144.53 1541,3115.53 1541,3058 1542,3057 1633,3057 1634,3058 1634,3177.75 1656.25,3200 1723.32,3200 1748,3175.32 1748,3135 1773,3110 1775,3110 ; C7.1@1695,2754.88 1752.5,2812.38 1752.5,2904.32 1755,2906.82 1755,3090 1775,3110 ; v1(1930,3149) 1930,3120 1940,3110 1775,3110 ; v1(2305,3158) 2305,3250 2315,3260 2305,3270 2325,3270 2415,3360 ; v1(2785,3155) 2791,3155 C12.2@2846,3100 ; v1(2830,2920) 2830,2979.61 U13.3@2934.84,3084.45 2889.55,3084.45 ; C12.2@2830.12,3100 C12.2@2846,3100 ; R4.1@3045,3620.47 3015.47,3650 C2.2@2950.12,3650 2950.12,3617 2866,3532.88 2866,3420 2915,3371 D5.2@2915,3341 2954,3341 2955,3340 2955,3319.5 2985,3289.5 2985,3235 2982,3232 2900,3232 2884,3216 2884,3090 ; C12.2@2846,3100 2874,3100 2884,3090 ; C12.2@2846,3100 2861.55,3084.45 2885,3084.45 ; 2884,3090 2884,3085.45 2885,3084.45 ; 2884,3090 2889.55,3084.45 ; 2885,3084.45 2889.55,3084.45
  Signal Layer 2 w15: v1(1020,3585) 1040,3585 1040,3622.5 1074.32,3622.5 1116.82,3580 1124.19,3580 1124.91,3580.72 1191.81,3580.72 1285,3487.53 1285,3345 v1(1265,3325)
  Signal Layer 2 w20: v1(1930,3149) 1935,3144 1935,3030 1980.36,2984.64 2024.29,2984.64 2197.64,3158 v1(2305,3158) 2642.36,3158 2660.36,3140 2770,3140 v1(2785,3155)
  Signal Layer 1 w20: v1(1444,2296) 1444,2251 1545,2150 ; U1.3@1620,2075 1545,2150 ; v1(1930,3149) 1930,3095 1920,3085 1735,3085 1664,3014 1664,2667 1545,2548 1545,2150 ; v1(2580.64,1950.64) 2580,1951.28 2580,2762.84 2737.16,2920 v1(2830,2920)
  Solder Side w15: v1(1210,2296) v1(1444,2296)
A6: J1.1 R18.1 | length 2168.5
  Component Side w15: v1(2654,3265) 2685.47,3265 R18.1@2730.47,3310
  Signal Layer 2 w20: v1(2335,3431.5) 2342.5,3431.5 2509,3265 v1(2654,3265)
  Solder Side w15: J1.1@1409.21,3824.09 1455.12,3870 1654,3870 1686.5,3837.5 1686.5,3762.5 1699,3750 1760.5,3750 1821,3689.5 1821,3637.76 1822.5,3636.26 1822.5,3617.62 1790,3585.12 1790,3541.82 1797.5,3534.32 1797.5,3500.68 1810.68,3487.5 1829.32,3487.5 1843.85,3502.03 1876.95,3502.03 1920,3458.98 1920,3340 2075.97,3184.03 2219.03,3184.03 2335,3300 v1(2335,3431.5)
A7: J1.11
CAN0H: J1.13 U5.7 | length 3330.3
  Component Side w10: U5.7@1364.84,1757.91 1364.84,1710 v1(1380,1694.84)
  Signal Layer 1 w20: v1(1285,4090) 1285,4039.64 1330,3994.64 1330,2009.64 1260,1939.64 1260,1907 1289.5,1877.5 1289.5,1785.34 v1(1380,1694.84)
  Solder Side w15: v1(1285,4090) 1898.98,4090 1899.96,4089.02 J1.13@1899.96,3935.91
CAN0L: J1.12 U5.6 | length 3074
  Component Side w10: v1(1330,1695) 1330,1694.84 1330.08,1694.92 1345.16,1710 U5.6@1345.16,1757.91
  Signal Layer 2 w20: v1(1310,4050) 1330,4030 1330,1990.36 1270,1930.36 1270,1909.64 1307.5,1872.14 1307.5,1776.29 1330,1753.79 v1(1330,1695)
  Solder Side w15: v1(1310,4050) 1785,4050 1790.91,4044.09 J1.12@1790.91,3935.91
CAN0RX: "Teensy 3.6.9" U5.4 | length 1528.3
  Component Side w10: v1(1295,1920) 1325.47,1920 U5.4@1325.47,1872.09
  Component Side w15: v1(1775,2895) 1780,2895 1815,2860
  Signal Layer 2 w20: v1(1295,1920) 1405,2030 1638.64,2030 1663.64,2055 1765,2055 1765,2091.73 1750,2106.73 1750,2795.36 1765,2810.36 1765,2900 1770,2895 v1(1775,2895)
CAN0TX: "Teensy 3.6.10" U5.1 | length 1493.4
  Component Side w10: U5.1@1384.53,1872.09 1384.53,1920 v1(1415,1920)
  Component Side w15: v1(1777.5,2990) 1777.5,2992.5 1780,2995 1815,2960
  Signal Layer 1 w20: v1(1415,1920) 1500,2005 1715,2005 1765,2055 1765,2759.64 1750,2774.64 1750,2964.09 1775.91,2990 v1(1777.5,2990)
"CAN1 Switch": "Teensy 3.6.11" U6.8 U6.19 | length 1106.6
  Component Side w11.81: U6.19@1900.94,3673.15 1900.94,3697 1903.94,3700 ; 1919.41,3305.59 1919.41,3430.5 U6.8@1919.41,3503 ; U6.8@1920.63,3515.67 U6.8@1920.63,3504 ; U6.8@1919.41,3503 1920.63,3503 U6.8@1920.63,3504 ; U6.8@1919.41,3503 1919.41,3504 U6.8@1920.63,3504
  Component Side w15: 1815,3060 v1(1860,3060) ; 1903.94,3700 v1(2015,3700) ; v1(1906.94,3245) 1906.94,3293.12 1919.41,3305.59 ; 1919.41,3430.5 1959.32,3430.5 1988.82,3460 v1(2000,3460)
  Signal Layer 1 w20: v1(2000,3460) 2014,3460 2025,3471 2025,3509.64 2035,3519.64 2035,3540.36 2015,3560.36 v1(2015,3700)
  Solder Side w15: v1(1860,3060) 1872.82,3060 1965,3152.18 1965,3220 1940,3245 v1(1906.94,3245)
CAN1H: J1.5 U8.7 | length 4527.9
  Component Side w10: U8.7@2888.73,1762.91 2888.73,1737.07 2915.8,1710 v1(2945,1710)
  Signal Layer 2 w20: J1.5@1845.43,3824.09 1845.31,3824.21 1845.31,4065.31 2660.9,4065.31 2669.69,4074.1 2669.69,4114.1 2773.82,4218.23 3198.23,4218.23 3198.23,3583.23 3036.15,3583.23 2945,3492.08 2945,2053.67 3000,1998.67 3000,1939.64 2945,1884.64 v1(2945,1710)
CAN1L: J1.10 U8.6 | length 4593
  Component Side w10: U8.6@2869.05,1762.91 2869.05,1710 2870,1709.05 2868,1707.05 2870,1705.05 v1(2870,1702.81)
  Signal Layer 1 w20: J1.10@1572.8,3935.91 1572.8,3947.8 1699.1,4074.1 2600.31,4074.1 2609.1,4065.31 2660.9,4065.31 2669.69,4074.1 2669.69,4114.69 2773.23,4218.23 3198.23,4218.23 3198.23,3583.23 3036.15,3583.23 2945,3492.08 2945,1955.36 2940,1950.36 2940,1929.64 2945,1924.64 2945,1780.05 2870,1705.05 v1(2870,1702.81)
CAN1RX: "Teensy 3.6.48" U8.4 | length 1284
  Component Side w10: U8.4@2849.36,1877.09 v1(2849.36,1930.64)
  Component Side w15: 2415,1160 2465,1210 v1(2483.5,1210)
  Signal Layer 2 w20: v1(2483.5,1210) 2483.5,1178.5 2500.18,1161.82 2795,1161.82 2795,1876.28 v1(2849.36,1930.64)
CAN1TX: "Teensy 3.6.47" U8.1 | length 1413.7
  Component Side w10: U8.1@2908.42,1877.09 2908.42,1933.42 v1(2915,1940)
  Component Side w15: 2415,1060 2420,1055 v1(2465,1055)
  Signal Layer 1 w20: v1(2465,1055) 2467.5,1057.5 2467.5,1162.5 2792.5,1162.5 2792.5,1867.5 2850.92,1867.5 2915,1931.58 v1(2915,1940)
CAN2H: J1.3 U6.7 U9.7 | length 1117.9
  Component Side w10: U9.7@1192.09,3663.31 1225,3663.31
  Component Side w11.81: 1900.94,3480 U6.7@1900.94,3515.67
  Component Side w14.76: 1225,3663.31 v1(1225,3720)
  Component Side w15: v1(1888,3453) 1888,3467.06 1900.94,3480
  Signal Layer 1 w20: J1.3@1627.32,3824.09 1638.2,3824.09 1825,3637.29 1825,3616.58 1813,3604.58 1813,3552.36 1845,3520.36 1845,3484.17 1876.17,3453 v1(1888,3453)
  Solder Side w15: v1(1225,3720) 1247.02,3720 1275,3747.98 1535.2,3747.98 1540.68,3742.5 1559.32,3742.5 1627.32,3810.5 J1.3@1627.32,3824.09
CAN2H/J1708+: J1.15 U6.6 | length 915.3
  Component Side w11.81: 1865,3431 1865,3488.74 1881.26,3505 U6.6@1881.26,3515.67
  Component Side w15: v1(1825,3420) 1876,3420 1865,3431
  Signal Layer 1 w20: v1(1825,3420) 1917,3420 1937,3400 1975,3438 1975,3489.14 1961,3503.14 1961,3518.64 1960,3519.64 1960,3547 1985,3572 1985,3755.51 2009.02,3779.53 2009.02,3850.35 2094.57,3935.91 J1.15@2118.07,3935.91
CAN2L: J1.4 U6.20 U9.6 | length 922.6
  Component Side w10: U9.6@1192.09,3643.62 1240,3643.62 1245,3648.62 1245,3750 1525,3750 1540,3765 v1(1550,3765)
  Component Side w11.81: v1(1868.76,3747.84) 1881.26,3735.34 U6.20@1881.26,3673.15
  Signal Layer 2 w20: v1(1550,3765) 1677.28,3765 J1.4@1736.38,3824.09 1812.63,3747.84 v1(1868.76,3747.84)
  Signal Layer 1 w20: v1@1868.42,3747.84 v1(1868.76,3747.84)
CAN2L/J1708-: J1.14 U6.1 | length 498.3
  Component Side w11.81: 1841,3705 1841,3633.78 U6.1@1841.89,3633.78
  Component Side w15: v1@1793,3870 1793,3753 1841,3705
  Signal Layer 1 w20: v1(1795,3870) 1797.36,3872.36 1945.47,3872.36 J1.14@2009.02,3935.91
CAN2RX: U9.4 U14.2 | length 1706.6
  Component Side w10: v1(1065,3585) 1065,3611.02 U9.4@1077.91,3623.94
  Component Side w15: v1(2330,3663.31) 2330,3650 2334.41,3645.59 U14.2@2381.89,3645.59
  Solder Side w15: v1(1065,3585) 1065,3696.98 1070,3701.98 1115.16,3701.98 1303.18,3890 1740,3890 1799,3831 1799,3762 1902.59,3658.41 2325.1,3658.41 v1(2330,3663.31)
CAN2TX: U9.1 U14.1 | length 2213.7
  Component Side w10: v1(1028,3764) 1077,3715 U9.1@1077,3682.99
  Component Side w15: v1(2336.3,3705) 2336.3,3690 2355.12,3671.18 U14.1@2381.89,3671.18
  Solder Side w15: v1(1028,3764) 1028,4068 1073,4113 1933,4113 1946,4100 1946,3909 1908,3871 1908,3775 1940.5,3742.5 2283.8,3742.5 2321.3,3705 v1(2336.3,3705)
